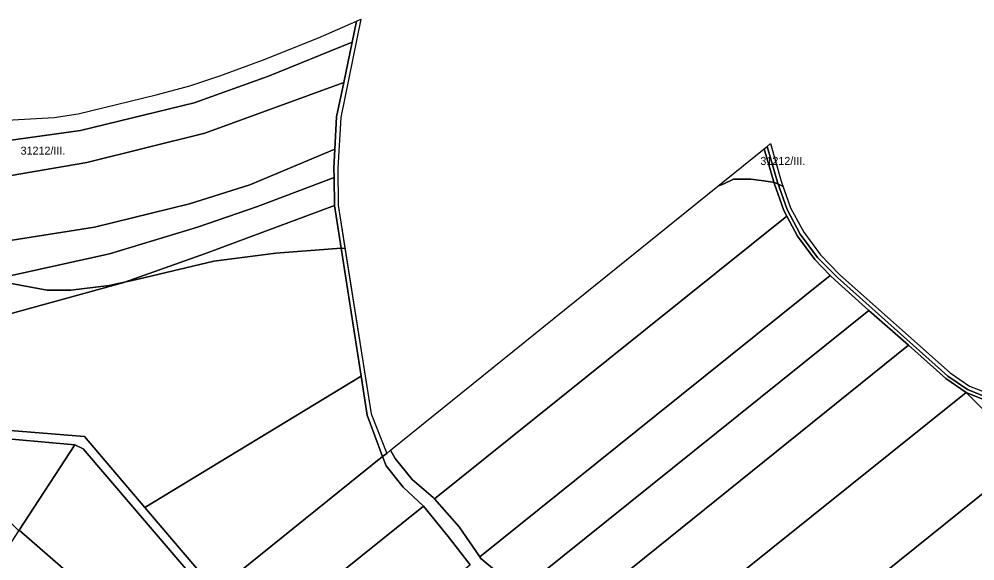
# Model space of a CAD drawing. Extents: x -541351 to -537540, y -1162694 to -1159725.
# Drawn here: x -539463 to -538870, y -1160275 to -1159939 of the extents above; entities that cross this region are included whole.
import ezdxf

# ---------------------------------------------------------------- set-up
doc = ezdxf.new("R2010")
doc.units = 0
for name, color, linetype in [('95560013', 7, 'Continuous'), ('95610013', 7, 'Continuous'), ('95630013', 7, 'Continuous'), ('95640013', 7, 'Continuous'), ('95660013', 7, 'Continuous')]:
    doc.layers.add(name, color=color, linetype=linetype)

msp = doc.modelspace()

# ---------------------------------------------------------------- linework, layer by layer
at = {"layer": '95560013'}
for points in [[(-539308.49, -1159974.08), (-539354.55, -1159990.5), (-539425.35, -1160007.86), (-539482.04, -1160015.57), (-539474.65, -1160001.49), (-539441.58, -1159999.6), (-539426.66, -1159997.49), (-539378.27, -1159985.56), (-539357.29, -1159979.97), (-539338.63, -1159973.85), (-539312.29, -1159964.05), (-539277.38, -1159950.13), (-539253.79, -1159939.77), (-539256.52, -1159952.89)], [(-539482.04, -1160015.57), (-539425.35, -1160007.86), (-539354.55, -1159990.5), (-539308.49, -1159974.08), (-539256.52, -1159952.89), (-539261.76, -1159978), (-539348.12, -1160009.46), (-539421.4, -1160027.65), (-539494.95, -1160040.2), (-539486.82, -1160024.7)], [(-539261.76, -1159978), (-539266.2, -1159999.29), (-539267.32, -1160019.26), (-539320.05, -1160041.46), (-539357.51, -1160053.36), (-539416.53, -1160067.73), (-539516.34, -1160083.61), (-539513.23, -1160077.01), (-539504.15, -1160057.74), (-539499.27, -1160048.44), (-539494.95, -1160040.2), (-539421.4, -1160027.65), (-539348.12, -1160009.46)], [(-539516.34, -1160083.61), (-539416.53, -1160067.73), (-539357.51, -1160053.36), (-539320.05, -1160041.46), (-539267.32, -1160019.26), (-539267.84, -1160031.16), (-539267.74, -1160037), (-539315.38, -1160054.86), (-539352.56, -1160067.89), (-539407.25, -1160084.31), (-539518.09, -1160108.82), (-539519.03, -1160104.35), (-539519.41, -1160090.12)], [(-539206.08, -1160235.73), (-539219.19, -1160224.51), (-539229.72, -1160211.49), (-539232.65, -1160206.32), (-539000.5, -1160019.14), (-538994.28, -1160040.49), (-538988.26, -1160057.45), (-538986.39, -1160060.99), (-539096.18, -1160148.92), (-539205.45, -1160236.44)], [(-539347.53, -1160084.05), (-539398.26, -1160102.11), (-539512.88, -1160133.53), (-539518.09, -1160108.82), (-539407.25, -1160084.31), (-539352.56, -1160067.89), (-539315.38, -1160054.86), (-539267.74, -1160037), (-539267.44, -1160054.36)], [(-539512.88, -1160133.53), (-539398.26, -1160102.11), (-539347.53, -1160084.05), (-539267.44, -1160054.36), (-539250.94, -1160160.23), (-539385.29, -1160241.92), (-539422.88, -1160197.87), (-539502.48, -1160191.42), (-539505.96, -1160190.04), (-539505.45, -1160182.31), (-539504.78, -1160171.93), (-539506.16, -1160165.16)], [(-539189.95, -1160253.97), (-539205.45, -1160236.44), (-539096.18, -1160148.92), (-538986.39, -1160060.99), (-538979.86, -1160073.37), (-538969.1, -1160087.93), (-538959.62, -1160097.82), (-539067.6, -1160184.51), (-539177.24, -1160272.53)], [(-538959.62, -1160097.82), (-538956.49, -1160100.62), (-538935.46, -1160119.47), (-539152.16, -1160293.52), (-539155.94, -1160290.64), (-539176.56, -1160273.52), (-539177.24, -1160272.53), (-539067.6, -1160184.51)], [(-538910.96, -1160141.13), (-539127.06, -1160315.25), (-539152.16, -1160293.52), (-538935.46, -1160119.47)], [(-539094.38, -1160341.15), (-539127.06, -1160315.25), (-538910.96, -1160141.13), (-538887.73, -1160161.8), (-538875.02, -1160170.41), (-539091.17, -1160343.7)], [(-539341.25, -1160293.53), (-539385.29, -1160241.92), (-539250.94, -1160160.23), (-539247.17, -1160184.44), (-539237.55, -1160210.2)], [(-538831.18, -1160196.34), (-538821.3, -1160198.29), (-539040.21, -1160374.33), (-539048.36, -1160373.06), (-539056.23, -1160370.78), (-539064.1, -1160367.35), (-539079.28, -1160354.4), (-539091.17, -1160343.7), (-538875.02, -1160170.41), (-538863.17, -1160182.34)], [(-539463.53, -1160256.34), (-539494.99, -1160225.44), (-539511.16, -1160209.5), (-539506.72, -1160201.77), (-539506.35, -1160196.13), (-539502.7, -1160196.39), (-539428.87, -1160202.88), (-539463.26, -1160255.92)], [(-538988.93, -1160377.95), (-539008.72, -1160374.73), (-539040.21, -1160374.33), (-538821.3, -1160198.29), (-538777.62, -1160206.88), (-538729.24, -1160212.16), (-538718.14, -1160212.05), (-538928.34, -1160381.56), (-538948.98, -1160379.96)], [(-539428.87, -1160202.88), (-539423.65, -1160205.41), (-539314.44, -1160333.03), (-539338.32, -1160364.79), (-539463.26, -1160255.92)], [(-539315.32, -1160323.92), (-539341.25, -1160293.53), (-539237.55, -1160210.2), (-539235.42, -1160215.92), (-539224.77, -1160229.29), (-539212.25, -1160241.09)], [(-539196.85, -1160259.88), (-539183.21, -1160277.53), (-539281.49, -1160362.9), (-539283.48, -1160361.23), (-539315.32, -1160323.92), (-539212.25, -1160241.09)]]:
    msp.add_lwpolyline(points, close=True, dxfattribs=at)
for points in [[(-539502.48, -1160191.42), (-539422.88, -1160197.87), (-539385.29, -1160241.92), (-539341.25, -1160293.53), (-539315.32, -1160323.92), (-539283.48, -1160361.23), (-539281.49, -1160362.9), (-539254.28, -1160385.71), (-539225.75, -1160409.65), (-539187.06, -1160442.11), (-539176.75, -1160450.77), (-539132.63, -1160486.38), (-539067.96, -1160538.57), (-538988.47, -1160602.73), (-538983.69, -1160602.58), (-538814.47, -1160413.51)], [(-539314.44, -1160333.03), (-539423.65, -1160205.41), (-539428.87, -1160202.88), (-539502.7, -1160196.39)]]:
    msp.add_lwpolyline(points, dxfattribs=at)
at = {"layer": '95610013'}
msp.add_lwpolyline([(-539338.32, -1160364.79), (-539393.71, -1160438.45), (-539395.56, -1160440.92), (-539397.21, -1160443.12), (-539416.61, -1160431.81), (-539432.78, -1160417.52), (-539479.17, -1160360.89), (-539508.32, -1160325.42), (-539463.53, -1160256.34), (-539463.26, -1160255.92)], close=True, dxfattribs=at)
at = {"layer": '95630013'}
msp.add_lwpolyline([(-538863.2, -1160175.22), (-538875.02, -1160170.41), (-538887.73, -1160161.8), (-538910.96, -1160141.13), (-538935.46, -1160119.47), (-538956.49, -1160100.62), (-538959.62, -1160097.82), (-538969.1, -1160087.93), (-538979.86, -1160073.37), (-538986.39, -1160060.99), (-538988.26, -1160057.45), (-538994.28, -1160040.49), (-539000.5, -1160019.14), (-538998.75, -1160017.67), (-538992.36, -1160039.83), (-538986.31, -1160056.85), (-538978.16, -1160072.22), (-538967.47, -1160086.7), (-538955.06, -1160099.12), (-538886.36, -1160160.36), (-538874.16, -1160168.65), (-538859.9, -1160174.32)], dxfattribs=at)
at = {"layer": '95640013'}
for points in [[(-539266.2, -1159999.29), (-539261.76, -1159978), (-539256.52, -1159952.89), (-539253.79, -1159939.77), (-539251.01, -1159938.59), (-539263.64, -1159999.6), (-539265.33, -1160031.19), (-539265.24, -1160054.12), (-539244.59, -1160183.77), (-539235.05, -1160208.26), (-539237.55, -1160210.2), (-539247.17, -1160184.44), (-539250.94, -1160160.23), (-539267.44, -1160054.36), (-539267.74, -1160037), (-539267.84, -1160031.16), (-539267.32, -1160019.26)], [(-538848.02, -1160174.62), (-538850.66, -1160176.7), (-538859.9, -1160174.32), (-538874.16, -1160168.65), (-538886.36, -1160160.36), (-538955.06, -1160099.12), (-538967.47, -1160086.7), (-538978.16, -1160072.22), (-538986.31, -1160056.85), (-538992.36, -1160039.83), (-538998.75, -1160017.67), (-538996.64, -1160015.93), (-538990.06, -1160039.15), (-538984.11, -1160055.68), (-538975.92, -1160070.9), (-538965.59, -1160084.97), (-538953.46, -1160097.34), (-538885.01, -1160158.23), (-538872.92, -1160166.48), (-538859.62, -1160171.76)], [(-538863.2, -1160175.22), (-538860.3, -1160178.14), (-538829.68, -1160191.54), (-538816.21, -1160194.19), (-538821.3, -1160198.29), (-538831.18, -1160196.34), (-538863.17, -1160182.34), (-538875.02, -1160170.41)]]:
    msp.add_lwpolyline(points, close=True, dxfattribs=at)
msp.add_lwpolyline([(-539183.21, -1160277.53), (-539196.85, -1160259.88), (-539212.25, -1160241.09), (-539224.77, -1160229.29), (-539235.42, -1160215.92), (-539237.55, -1160210.2), (-539235.05, -1160208.26), (-539232.65, -1160206.32), (-539229.72, -1160211.49), (-539219.19, -1160224.51), (-539206.08, -1160235.73), (-539205.45, -1160236.44), (-539189.95, -1160253.97), (-539177.24, -1160272.53), (-539176.56, -1160273.52), (-539155.94, -1160290.64)], dxfattribs=at)
at = {"layer": '95660013'}
for points in [[(-539474.65, -1160001.49), (-539441.58, -1159999.6), (-539426.66, -1159997.49), (-539378.27, -1159985.56), (-539357.29, -1159979.97), (-539338.63, -1159973.85), (-539312.29, -1159964.05), (-539277.38, -1159950.13), (-539253.79, -1159939.77), (-539251.01, -1159938.59), (-539263.64, -1159999.6), (-539265.33, -1160031.19), (-539265.24, -1160054.12), (-539261, -1160080.74), (-539266, -1160081), (-539303.87, -1160084), (-539342.37, -1160089), (-539389.5, -1160100), (-539407.37, -1160104), (-539431.31, -1160107), (-539445.87, -1160107), (-539483, -1160100)], [(-539483, -1160100), (-539445.87, -1160107), (-539431.31, -1160107), (-539407.37, -1160104), (-539389.5, -1160100), (-539342.37, -1160089), (-539303.87, -1160084), (-539266, -1160081), (-539261, -1160080.74), (-539244.59, -1160183.77), (-539235.05, -1160208.26), (-539232.65, -1160206.32), (-539029.3, -1160042.36), (-539026.12, -1160041), (-539019.69, -1160038), (-539008.87, -1160038), (-539000.71, -1160039.11), (-538994.19, -1160040), (-538988.92, -1160042.31), (-538984.11, -1160055.68), (-538975.92, -1160070.9), (-538965.59, -1160084.97), (-538953.46, -1160097.34), (-538885.01, -1160158.23), (-538872.92, -1160166.48), (-538859.62, -1160171.76)]]:
    msp.add_lwpolyline(points, dxfattribs=at)
msp.add_lwpolyline([(-538996.64, -1160015.93), (-538990.06, -1160039.15), (-538988.92, -1160042.31), (-538994.19, -1160040), (-539000.71, -1160039.11), (-539008.87, -1160038), (-539019.69, -1160038), (-539026.12, -1160041), (-539029.3, -1160042.36), (-539000.5, -1160019.14), (-538998.75, -1160017.67)], close=True, dxfattribs=at)

# ---------------------------------------------------------------- texts
for rotation, p in [(360, (-539462.5, -1160022.79)), (0, (-539002.9, -1160029.15))]:
    msp.add_text('31212/III.', height=5, rotation=rotation, dxfattribs=at).set_placement(p)

doc.saveas('drawing.dxf')
